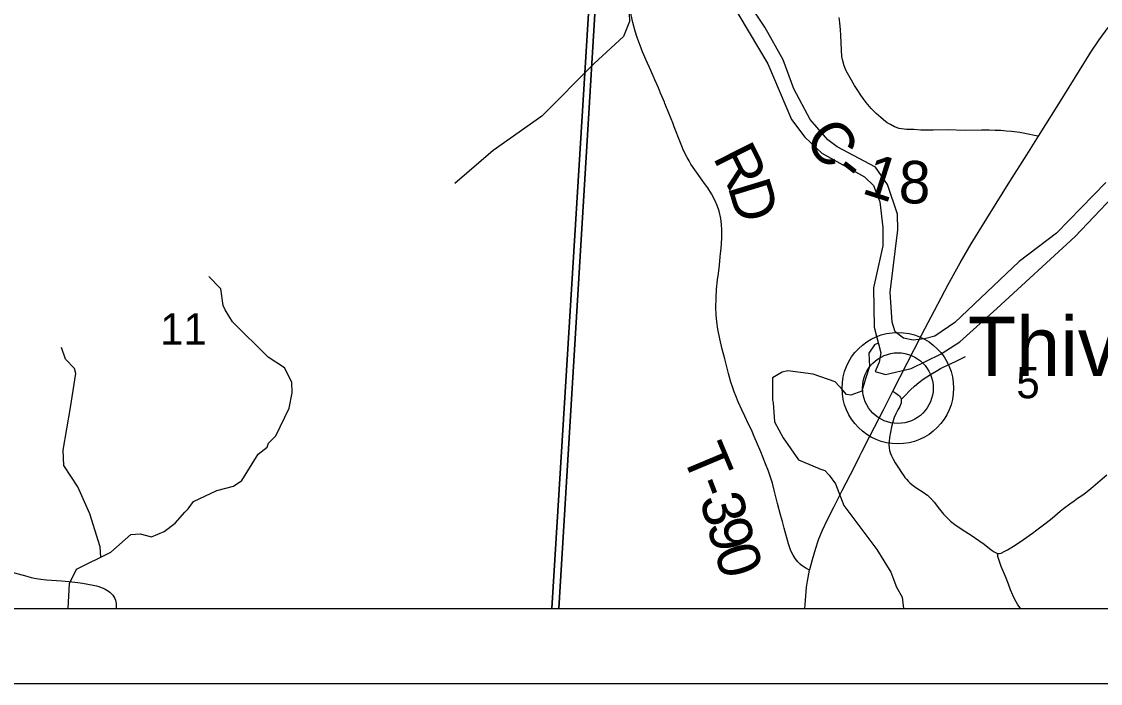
# Model space of a CAD drawing. Extents: x 0 to 34, y 0 to 22.
# Drawn here: x 4.109 to 5.548, y 14 to 14.883 of the extents above; entities that cross this region are included whole.
import ezdxf

# ---------------------------------------------------------------- set-up
doc = ezdxf.new("R2010")
doc.units = 0
for name, color, linetype in [('Default', 7, 'Continuous'), ('GM_X_County_Road', 7, 'Continuous'), ('GM_X_County_Road_Text', 7, 'Continuous'), ('GM_X_Major_River', 7, 'Continuous'), ('GM_X_Minor_River', 7, 'Continuous'), ('GM_X_Section_Text', 7, 'Continuous'), ('GM_X_State_Route', 7, 'Continuous'), ('GM_X_Township_Road', 7, 'Continuous'), ('GM_X_Township_Road_Text', 7, 'Continuous'), ('GM_X_Unincorporated', 7, 'Continuous'), ('GM_X_Unincorporated_Location', 7, 'Continuous'), ('GM_X_Unincorporated_Text', 7, 'Continuous'), ('SH_Data', 7, 'Continuous'), ('SH_Text', 7, 'Continuous')]:
    doc.layers.add(name, color=color, linetype=linetype)

msp = doc.modelspace()

# ---------------------------------------------------------------- linework, layer by layer
at = {"layer": 'Default'}
for points in [[(2.1, 16.1239), (2.1, 14.1), (4.8164, 14.1), (4.8734, 15.0246), (4.8987, 15.3279), (4.9458, 15.9099), (4.9525, 15.9829), (4.6644, 15.9921), (3.9292, 16.0191), (3.6368, 16.0331), (2.1721, 16.1195)], [(3.7808, 14.1), (4.8257, 14.1), (4.8777, 14.9601), (3.8368, 15.0128)], [(4.8257, 14.1), (5.8897, 14.1), (5.8935, 14.1589), (5.91, 14.4183), (5.9253, 14.6691), (5.9405, 14.9074), (4.8777, 14.9601)]]:
    msp.add_lwpolyline(points, close=True, dxfattribs=at)
msp.add_lwpolyline([(4.9458, 15.9099), (4.8987, 15.3279), (4.8734, 15.0246), (4.8164, 14.1), (8.0885, 14.1)], dxfattribs=at)
at = {"layer": 'GM_X_County_Road'}
for points in [[(5.4656, 14.7303), (5.4628, 14.7308), (5.4499, 14.7336), (5.4407, 14.7353), (5.4296, 14.7369), (5.4225, 14.7374), (5.4153, 14.738), (5.4079, 14.7383), (5.3998, 14.7386), (5.3898, 14.7386), (5.3681, 14.7383), (5.3442, 14.7388), (5.325, 14.7387), (5.3086, 14.7387), (5.2993, 14.7392), (5.2895, 14.7395), (5.28, 14.7409), (5.2738, 14.743), (5.2682, 14.7459), (5.264, 14.7483), (5.2591, 14.7521), (5.2553, 14.7553), (5.2491, 14.7608), (5.2424, 14.7676), (5.2358, 14.7753), (5.2317, 14.7806), (5.2286, 14.7851), (5.2245, 14.7913), (5.2202, 14.7981), (5.2143, 14.8083), (5.2093, 14.8176), (5.2065, 14.8245), (5.2046, 14.8309), (5.2035, 14.837), (5.2027, 14.8455), (5.202, 14.8652), (5.2017, 14.8726), (5.2008, 14.8819), (5.1996, 14.8887)], [(5.2715, 14.3903), (5.2755, 14.3876), (5.2773, 14.3863), (5.2789, 14.3849), (5.2804, 14.3834), (5.2816, 14.3818), (5.2821, 14.3806), (5.2825, 14.3792), (5.2826, 14.3776), (5.2825, 14.3762), (5.2823, 14.3746), (5.282, 14.3732), (5.2806, 14.3698), (5.2781, 14.3651), (5.2756, 14.36), (5.2733, 14.3549), (5.2715, 14.3493), (5.2697, 14.3424), (5.2683, 14.3352), (5.267, 14.3281), (5.2665, 14.3228), (5.2662, 14.3183), (5.2665, 14.3143), (5.2671, 14.3108), (5.2683, 14.3071), (5.2697, 14.3037), (5.2714, 14.3002), (5.2746, 14.2945), (5.2788, 14.2877), (5.2839, 14.2801), (5.2862, 14.2771), (5.2876, 14.2751), (5.2895, 14.2727), (5.2924, 14.2695), (5.2941, 14.2678), (5.2969, 14.2655), (5.3004, 14.2629), (5.3023, 14.2615), (5.3131, 14.2544), (5.3156, 14.2526), (5.3175, 14.2511), (5.3189, 14.2499), (5.3228, 14.246), (5.3265, 14.2419), (5.3337, 14.2326), (5.3392, 14.2259), (5.3437, 14.2209), (5.3482, 14.2167), (5.3542, 14.2122), (5.3654, 14.2046), (5.3757, 14.198), (5.386, 14.191), (5.3876, 14.1899)], [(5.4111, 14.1735), (5.4134, 14.1736), (5.4158, 14.1741), (5.4199, 14.176), (5.4242, 14.1783), (5.4345, 14.1847), (5.4458, 14.1922), (5.4576, 14.2006), (5.4635, 14.205), (5.469, 14.209), (5.4744, 14.2131), (5.4839, 14.2208), (5.4948, 14.2298), (5.4991, 14.2333), (5.5075, 14.2396), (5.5135, 14.2439), (5.518, 14.2471), (5.5221, 14.2499), (5.5267, 14.253), (5.5306, 14.2561), (5.5357, 14.2604), (5.548, 14.2709), (5.557, 14.2784)], [(5.3876, 14.1899), (5.3932, 14.1858), (5.4028, 14.1783), (5.4067, 14.1755), (5.4091, 14.1742), (5.4111, 14.1735)], [(5.4418, 14.1), (5.4376, 14.106), (5.4343, 14.1119), (5.4313, 14.1179), (5.4283, 14.1249), (5.4256, 14.1324), (5.4217, 14.1426), (5.4161, 14.1559), (5.4119, 14.168), (5.4116, 14.1694), (5.4113, 14.1708), (5.4111, 14.1735)], [(4.0929, 14.1495), (4.1159, 14.1431), (4.1218, 14.1415), (4.1285, 14.14), (4.1346, 14.139), (4.1421, 14.1382), (4.1619, 14.1369), (4.1717, 14.136), (4.184, 14.1346), (4.1902, 14.1338), (4.1973, 14.1326), (4.2042, 14.1313), (4.2086, 14.1302), (4.2119, 14.1292), (4.2149, 14.1282), (4.2178, 14.127), (4.2204, 14.1259), (4.2227, 14.1247), (4.2248, 14.1233), (4.2268, 14.1218), (4.2287, 14.1198), (4.2304, 14.1177), (4.2318, 14.1156), (4.2331, 14.1134), (4.234, 14.1111), (4.2345, 14.109), (4.2349, 14.1067), (4.2351, 14.1035), (4.2352, 14.1)]]:
    msp.add_lwpolyline(points, dxfattribs=at)
at = {"layer": 'GM_X_Major_River'}
for points in [[(5.5558, 14.6688), (5.4896, 14.6012), (5.4399, 14.563), (5.3541, 14.4817), (5.3273, 14.4637), (5.3137, 14.4602), (5.2986, 14.4582), (5.2858, 14.4608), (5.2744, 14.4695), (5.2705, 14.4823), (5.268, 14.5225), (5.2782, 14.6053), (5.2777, 14.6262), (5.2642, 14.6659), (5.2482, 14.689), (5.197, 14.7164), (5.1848, 14.7258), (5.1613, 14.7529), (5.1395, 14.7938), (5.1249, 14.8324), (5.1008, 14.8759), (5.0741, 14.9163), (5.0518, 14.9381), (5.0169, 14.9523)], [(5.0334, 14.9242), (5.0533, 14.9135), (5.1045, 14.827), (5.1363, 14.7528), (5.1538, 14.729), (5.1766, 14.7079), (5.2335, 14.6764), (5.2457, 14.6647), (5.2541, 14.6427), (5.2581, 14.6086), (5.2579, 14.5843), (5.2457, 14.5281), (5.2463, 14.4757), (5.2552, 14.4413), (5.253, 14.4287), (5.2478, 14.4162), (5.2614, 14.4125), (5.2958, 14.4206), (5.3358, 14.4398), (5.361, 14.4559), (5.41, 14.5006), (5.5146, 14.5968), (5.5898, 14.6758)]]:
    msp.add_lwpolyline(points, dxfattribs=at)
at = {"layer": 'GM_X_Minor_River'}
for points in [[(4.9226, 14.9829), (4.9151, 14.9737), (4.9104, 14.9387), (4.919, 14.9053), (4.9199, 14.8837), (4.912, 14.8635), (4.8728, 14.8276), (4.803, 14.757), (4.738, 14.7115), (4.687, 14.6672)], [(4.171, 14.1), (4.171, 14.1001), (4.1727, 14.1334), (4.182, 14.1525), (4.228, 14.1753), (4.2548, 14.1988), (4.267, 14.1995), (4.282, 14.1956), (4.2992, 14.203), (4.3139, 14.214), (4.3268, 14.2287), (4.3311, 14.2332), (4.3382, 14.2428), (4.3693, 14.2574), (4.3914, 14.2635), (4.4025, 14.2708), (4.4244, 14.3061), (4.4364, 14.3156), (4.4381, 14.3209), (4.4482, 14.3304), (4.466, 14.3675), (4.47, 14.3878), (4.4693, 14.4023), (4.4597, 14.4212), (4.4378, 14.4356), (4.3904, 14.4827), (4.3803, 14.4985), (4.3779, 14.5043), (4.3748, 14.5268), (4.3586, 14.5433)], [(5.2517, 14.4541), (5.2471, 14.452), (5.2392, 14.4409), (5.2403, 14.423), (5.235, 14.4067), (5.2298, 14.39), (5.2154, 14.3846), (5.2097, 14.3857), (5.2048, 14.3914), (5.1946, 14.4024), (5.1651, 14.413), (5.1311, 14.4171), (5.1235, 14.4156), (5.1107, 14.4079), (5.1107, 14.3783), (5.1118, 14.3745), (5.1137, 14.3494), (5.1251, 14.3278), (5.1455, 14.2985), (5.173, 14.2868)], [(4.2145, 14.1686), (4.2139, 14.1822), (4.2001, 14.2263), (4.1838, 14.2626), (4.165, 14.2909), (4.1645, 14.3114), (4.1742, 14.3684), (4.1812, 14.4138), (4.1795, 14.4203), (4.1674, 14.4328), (4.1622, 14.4482)], [(5.1728, 14.2869), (5.1807, 14.2842), (5.1864, 14.2781), (5.1947, 14.2663), (5.2061, 14.2375), (5.25, 14.179), (5.2689, 14.1487), (5.2761, 14.1286), (5.2837, 14.1153), (5.2855, 14.1)]]:
    msp.add_lwpolyline(points, dxfattribs=at)
at = {"layer": 'GM_X_State_Route'}
for points in [[(5.4656, 14.7303), (5.493, 14.7738), (5.5204, 14.818), (5.5356, 14.8425), (5.5467, 14.859), (5.5586, 14.8757)], [(5.1931, 14.2362), (5.1944, 14.239), (5.2038, 14.2576), (5.2201, 14.2893), (5.2275, 14.3039), (5.2301, 14.309), (5.2413, 14.3308), (5.2588, 14.3653), (5.2715, 14.3903), (5.3098, 14.4647), (5.3313, 14.5061), (5.345, 14.5325), (5.3611, 14.5616), (5.376, 14.5868), (5.3967, 14.6207), (5.4277, 14.6699), (5.4501, 14.7055), (5.4656, 14.7303)], [(5.1719, 14.1902), (5.1728, 14.193), (5.1775, 14.2045), (5.1844, 14.2187), (5.1931, 14.2362)], [(5.1606, 14.1521), (5.164, 14.1653), (5.1686, 14.1807), (5.1719, 14.1902)], [(5.1538, 14.1), (5.1542, 14.1052), (5.1561, 14.1284), (5.1574, 14.1363), (5.1604, 14.1512), (5.1606, 14.1521)]]:
    msp.add_lwpolyline(points, dxfattribs=at)
at = {"layer": 'GM_X_Township_Road'}
for points in [[(5.1604, 14.1512), (5.1555, 14.1539), (5.1506, 14.157), (5.1476, 14.1593), (5.1445, 14.1624), (5.1411, 14.1669), (5.1383, 14.1713), (5.1353, 14.1772), (5.1321, 14.1865), (5.1266, 14.2073), (5.1242, 14.216), (5.1216, 14.2252), (5.1176, 14.2403), (5.1152, 14.2493), (5.113, 14.2581), (5.1106, 14.2673), (5.1087, 14.2739), (5.1054, 14.2832), (5.1016, 14.2931), (5.0951, 14.3092), (5.0908, 14.3195), (5.0863, 14.3297), (5.0826, 14.3383), (5.0789, 14.346), (5.0739, 14.3568), (5.07, 14.3653), (5.0651, 14.3761), (5.0619, 14.384), (5.0598, 14.3894), (5.0576, 14.3958), (5.0554, 14.4023), (5.052, 14.4136), (5.047, 14.4335), (5.0438, 14.4461), (5.0405, 14.4601), (5.038, 14.4729), (5.0364, 14.4827), (5.0355, 14.492), (5.0351, 14.502), (5.0355, 14.5144), (5.0363, 14.5262), (5.0376, 14.5386), (5.0386, 14.5471), (5.0399, 14.5583), (5.041, 14.5695), (5.0414, 14.5741), (5.0421, 14.5806), (5.0426, 14.5874), (5.0432, 14.5948), (5.0434, 14.6053), (5.0429, 14.6127), (5.0418, 14.6207), (5.0395, 14.6303), (5.0369, 14.6379), (5.0337, 14.6452), (5.0293, 14.6534), (5.0245, 14.6614), (5.0202, 14.6675), (5.017, 14.672), (5.007, 14.6855), (5.0019, 14.6933), (4.9994, 14.6975), (4.9969, 14.7019), (4.9921, 14.7114), (4.9897, 14.7172), (4.9879, 14.7217), (4.9797, 14.7432), (4.9777, 14.7485), (4.9757, 14.7537), (4.9718, 14.7635), (4.9673, 14.7743), (4.9666, 14.776), (4.9615, 14.7881), (4.9585, 14.7949), (4.9563, 14.8), (4.9539, 14.8057), (4.9516, 14.8109), (4.9467, 14.8222), (4.9441, 14.8279), (4.9419, 14.833), (4.9392, 14.8393), (4.9375, 14.8433), (4.9356, 14.8479), (4.9329, 14.8551), (4.9301, 14.8624), (4.9274, 14.8707), (4.9245, 14.8822), (4.9202, 14.9029)], [(5.2825, 14.3792), (5.2863, 14.3828), (5.2951, 14.3919), (5.3002, 14.397), (5.3059, 14.4016), (5.3119, 14.406), (5.3218, 14.4125), (5.3314, 14.4182), (5.3352, 14.4204), (5.3452, 14.4253), (5.3548, 14.4297), (5.3682, 14.4362)]]:
    msp.add_lwpolyline(points, dxfattribs=at)
at = {"layer": 'GM_X_Unincorporated'}
for radius in [0.0744, 0.0472]:
    msp.add_circle((5.2781, 14.3942), radius, dxfattribs=at)
at = {"layer": 'GM_X_Unincorporated_Location'}
msp.add_line((5.2781, 14.3942), (5.2781, 14.3942), dxfattribs=at)
at = {"layer": 'SH_Data'}
for p, q in [((2.1, 14.1), (8.9, 14.1)), ((2, 14), (9, 14))]:
    msp.add_line(p, q, dxfattribs=at)
at = {"layer": 'SH_Text'}
msp.add_lwpolyline([(2.1, 14.1), (8.0885, 14.1)], dxfattribs=at)

# ---------------------------------------------------------------- texts
at = {"layer": 'GM_X_County_Road_Text'}
for s, rotation, p in [('C', 309.0877, (5.151, 14.7253)), ('1', 342.3302, (5.2282, 14.6548)), ('8', 358.4168, (5.2787, 14.6413)), ('-', 322.1398, (5.1905, 14.6793))]:
    msp.add_text(s, height=0.0568, rotation=rotation, dxfattribs=at).set_placement(p)
at = {"layer": 'GM_X_Section_Text'}
for s, height, p in [('11', 0.04186, (4.2937, 14.4523)), ('5', 0.0419, (5.4362, 14.3807))]:
    msp.add_text(s, height=height, rotation=0, dxfattribs=at).set_placement(p)
at = {"layer": 'GM_X_Township_Road_Text'}
for s, rotation, p in [('R', 296.6427, (5.0307, 14.7025)), ('D', 286.9367, (5.0507, 14.6631)), ('T', 292.754, (4.9894, 14.3058)), ('-', 290.72, (5.0056, 14.2671)), ('3', 284.9968, (5.0134, 14.2467)), ('9', 285.5967, (5.0227, 14.2122)), ('0', 287.344, (5.0326, 14.1767))]:
    msp.add_text(s, height=0.0568, rotation=rotation, dxfattribs=at).set_placement(p)
at = {"layer": 'GM_X_Unincorporated_Text'}
msp.add_text('Thivener', height=0.07898, rotation=0, dxfattribs=at).set_placement((5.3716, 14.4105))

doc.saveas('drawing.dxf')
